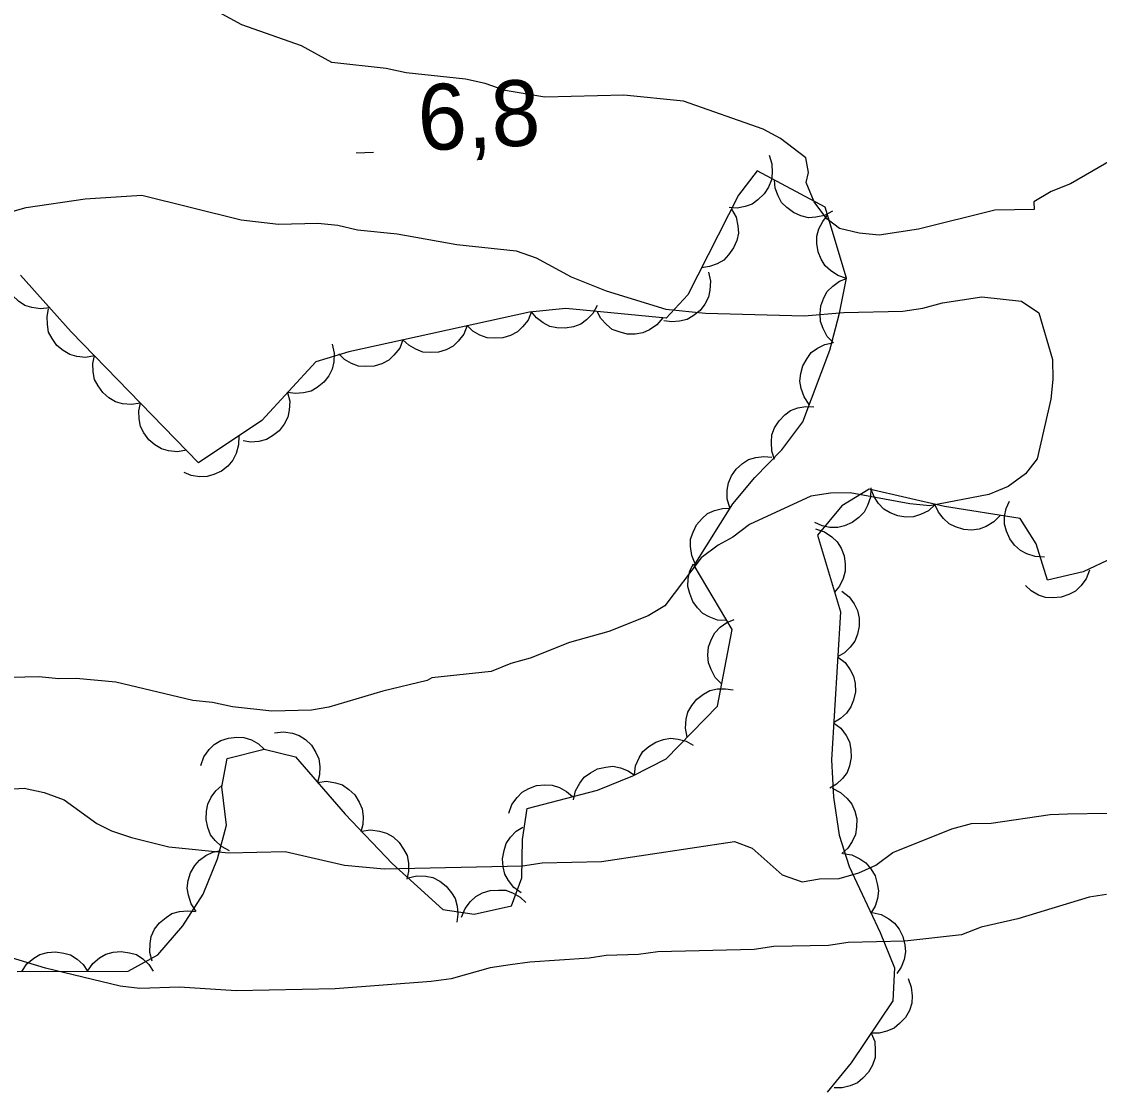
# Model space of a CAD drawing. Extents: x 336540 to 340074, y 5572036 to 5573747.
# Drawn here: x 337234.82 to 337283.95, y 5572869.46 to 5572918.23 of the extents above; entities that cross this region are included whole.
import ezdxf

# ---------------------------------------------------------------- set-up
doc = ezdxf.new("R2010")
doc.units = 0
for name, color, linetype in [('Niveau 2', 7, 'Continuous'), ('Niveau 3', 7, 'Continuous'), ('Niveau 44', 7, 'Continuous')]:
    doc.layers.add(name, color=color, linetype=linetype)

msp = doc.modelspace()

# ---------------------------------------------------------------- linework, layer by layer
at = {"layer": 'Niveau 2'}
for points in [[(337284.86, 5572912.13), (337282.63, 5572910.84), (337281.74, 5572910.48), (337280.96, 5572910.01), (337280.97, 5572909.67), (337279.17, 5572909.63), (337275.7, 5572908.76), (337273.9, 5572908.5), (337273, 5572908.59), (337272.09, 5572908.79), (337271.52, 5572909.23), (337270.94, 5572910.01), (337270.58, 5572910.9), (337270.68, 5572911.35), (337270.56, 5572912.02), (337269.41, 5572912.9), (337268.61, 5572913.33), (337264.98, 5572914.6), (337262.27, 5572914.88), (337258.67, 5572914.79), (337256.86, 5572915.09), (337255.95, 5572915.41), (337255.05, 5572915.61), (337252.34, 5572915.89), (337251.43, 5572916.09), (337248.95, 5572916.37), (337247.58, 5572917.13), (337244.85, 5572918.08), (337243.26, 5572918.95)], [(337234.12, 5572909.5), (337235.02, 5572909.75), (337237.71, 5572910.15), (337240.3, 5572910.32), (337244.83, 5572909.19), (337246.52, 5572909), (337248.32, 5572909.04), (337249.23, 5572908.95), (337250.13, 5572908.74), (337251.94, 5572908.56), (337254.65, 5572908.06), (337257.36, 5572907.78), (337258.27, 5572907.46), (337259.87, 5572906.6), (337261.46, 5572905.96), (337264.18, 5572905.12), (337265.99, 5572904.94), (337270.49, 5572904.81), (337272.29, 5572904.97), (337274.99, 5572905.03), (337275.89, 5572905.16), (337276.79, 5572905.41), (337278.58, 5572905.68), (337280.39, 5572905.49), (337281.19, 5572904.95), (337281.8, 5572902.82), (337281.82, 5572901.92), (337281.73, 5572901.02), (337281.11, 5572898.3)], [(337281.11, 5572898.3), (337280.57, 5572897.61), (337279.79, 5572897.03), (337278.9, 5572896.67), (337276.21, 5572896.16), (337275.3, 5572896.25), (337272.59, 5572896.75), (337271.69, 5572896.73), (337270.79, 5572896.6), (337268, 5572895.3), (337267.23, 5572894.72), (337266.56, 5572894.36), (337265.79, 5572893.78), (337264.14, 5572891.6), (337263.37, 5572891.14), (337261.58, 5572890.42), (337259.79, 5572889.93), (337258, 5572889.21), (337257.11, 5572888.97), (337256.22, 5572888.61), (337253.52, 5572888.32), (337253.3, 5572888.2), (337251.28, 5572887.71), (337248.82, 5572886.98), (337248.03, 5572886.84), (337246.23, 5572886.8), (337244.43, 5572886.99), (337243.52, 5572887.19), (337242.62, 5572887.28), (337239.11, 5572888.11), (337237.3, 5572888.29), (337236.51, 5572888.27), (337235.61, 5572888.36), (337233.02, 5572888.3)], [(337232.24, 5572883.11), (337234.94, 5572883.28), (337235.84, 5572883.08), (337236.75, 5572882.76), (337238.24, 5572881.67), (337238.92, 5572881.34), (337239.83, 5572881.03), (337241.53, 5572880.61), (337244.24, 5572880.34), (337246.83, 5572880.4), (337249.54, 5572879.78), (337251.35, 5572879.6), (337257.65, 5572879.74), (337258.55, 5572879.88), (337261.25, 5572879.94), (337267.31, 5572880.86), (337268.11, 5572880.55), (337269.49, 5572879.34), (337270.4, 5572879.02), (337271.18, 5572879.15), (337272.08, 5572879.17), (337272.98, 5572879.42), (337273.76, 5572879.77), (337274.53, 5572880.35), (337277.21, 5572881.43), (337278.11, 5572881.67), (337279.01, 5572881.69), (337281.7, 5572882.09), (337282.49, 5572882.11), (337284.29, 5572882.15)], [(337284.26, 5572878.44), (337283.48, 5572878.31), (337280.23, 5572877.33), (337278.55, 5572876.95), (337277.66, 5572876.6), (337275.08, 5572876.31), (337272.49, 5572876.25), (337271.59, 5572876.12), (337269.11, 5572876.06), (337268.21, 5572875.93), (337263.82, 5572875.83), (337262.93, 5572875.7), (337261.46, 5572875.66), (337260.68, 5572875.53), (337257.98, 5572875.36)], [(337257.98, 5572875.36), (337257.08, 5572875.23), (337256.18, 5572875.09), (337254.39, 5572874.6), (337253.49, 5572874.47), (337249.11, 5572874.14), (337244.6, 5572874.04), (337242.01, 5572874.21), (337240.21, 5572874.16), (337239.31, 5572874.26), (337235.91, 5572875.08), (337234.21, 5572875.6)]]:
    msp.add_lwpolyline(points, dxfattribs=at)
at = {"layer": 'Niveau 3'}
msp.add_line((337250.06, 5572912.24), (337250.86, 5572912.28), dxfattribs=at)
at = {"layer": 'Niveau 44'}
for points in [[(337268.89, 5572912.14), (337269.02, 5572911.74), (337269.03, 5572911.33), (337269, 5572911.01), (337268.86, 5572910.68), (337268.67, 5572910.37), (337268.38, 5572910.11), (337268.12, 5572909.91), (337267.79, 5572909.8), (337267.43, 5572909.73), (337267.07, 5572909.75)], [(337234.61, 5572874.93), (337239.67, 5572874.95), (337241.02, 5572875.69), (337242.17, 5572877.01), (337243.09, 5572878.45), (337243.74, 5572880.07), (337244.16, 5572881.6), (337243.95, 5572883.34), (337244.18, 5572884.63), (337245.87, 5572885.07), (337247.3, 5572884.71), (337249.57, 5572882.1), (337251.7, 5572879.85), (337254.01, 5572877.76), (337255.44, 5572877.54), (337257.14, 5572877.92), (337257.61, 5572879.19), (337257.65, 5572880.95), (337257.86, 5572882.36), (337261.06, 5572883.19), (337262.68, 5572883.85), (337264.19, 5572884.62), (337266.53, 5572887.02), (337267.2, 5572890.52), (337265.48, 5572893.44), (337267.24, 5572896.24), (337268.24, 5572897.45), (337269.47, 5572898.7), (337270.42, 5572899.99), (337271.65, 5572903.25), (337272.1, 5572904.94), (337272.42, 5572906.53), (337271.44, 5572909.77), (337268.34, 5572911.42), (337267.5, 5572910.32), (337265.18, 5572905.78), (337264.2, 5572904.71), (337259.63, 5572905.15), (337257.96, 5572904.99), (337249.73, 5572903.18), (337248.23, 5572902.72), (337245.76, 5572900.04), (337242.88, 5572898.12), (337237.08, 5572904.08), (337234.77, 5572906.67)], [(337271.78, 5572909.59), (337271.42, 5572909.39), (337271.02, 5572909.31), (337270.69, 5572909.29), (337270.34, 5572909.37), (337270, 5572909.52), (337269.7, 5572909.75), (337269.46, 5572909.98), (337269.3, 5572910.29), (337269.17, 5572910.64), (337269.14, 5572911)], [(337267.18, 5572909.68), (337267.38, 5572909.32), (337267.46, 5572908.92), (337267.49, 5572908.59), (337267.41, 5572908.25), (337267.27, 5572907.91), (337267.04, 5572907.6), (337266.82, 5572907.36), (337266.52, 5572907.18), (337266.17, 5572907.06), (337265.81, 5572907.01)], [(337272.42, 5572906.52), (337272.02, 5572906.65), (337271.69, 5572906.88), (337271.44, 5572907.1), (337271.26, 5572907.4), (337271.12, 5572907.74), (337271.07, 5572908.12), (337271.06, 5572908.45), (337271.16, 5572908.78), (337271.33, 5572909.12), (337271.55, 5572909.4)], [(337236.1, 5572905.18), (337235.68, 5572905.13), (337235.28, 5572905.19), (337234.97, 5572905.29), (337234.67, 5572905.48), (337234.4, 5572905.74), (337234.2, 5572906.06), (337234.06, 5572906.35), (337234, 5572906.7), (337234.01, 5572907.07), (337234.1, 5572907.42)], [(337266.12, 5572906.8), (337266.21, 5572906.39), (337266.19, 5572905.99), (337266.12, 5572905.66), (337265.96, 5572905.35), (337265.74, 5572905.06), (337265.43, 5572904.82), (337265.16, 5572904.65), (337264.81, 5572904.57), (337264.45, 5572904.54), (337264.09, 5572904.59)], [(337271.83, 5572903.58), (337271.53, 5572903.88), (337271.35, 5572904.24), (337271.23, 5572904.55), (337271.21, 5572904.9), (337271.25, 5572905.27), (337271.39, 5572905.63), (337271.54, 5572905.92), (337271.79, 5572906.17), (337272.09, 5572906.39), (337272.42, 5572906.52)], [(337238.14, 5572902.99), (337237.73, 5572902.92), (337237.33, 5572902.96), (337237.01, 5572903.05), (337236.71, 5572903.23), (337236.43, 5572903.47), (337236.21, 5572903.78), (337236.05, 5572904.07), (337235.99, 5572904.42), (337235.98, 5572904.79), (337236.05, 5572905.14)], [(337258.06, 5572905.01), (337257.91, 5572904.62), (337257.65, 5572904.31), (337257.42, 5572904.08), (337257.1, 5572903.92), (337256.75, 5572903.81), (337256.37, 5572903.79), (337256.04, 5572903.81), (337255.71, 5572903.93), (337255.39, 5572904.12), (337255.13, 5572904.37)], [(337261.05, 5572905.29), (337260.85, 5572904.92), (337260.56, 5572904.63), (337260.3, 5572904.44), (337259.97, 5572904.31), (337259.6, 5572904.25), (337259.22, 5572904.27), (337258.9, 5572904.33), (337258.59, 5572904.5), (337258.29, 5572904.72), (337258.06, 5572905)], [(337264.04, 5572904.73), (337263.77, 5572904.4), (337263.43, 5572904.18), (337263.13, 5572904.04), (337262.79, 5572903.98), (337262.42, 5572903.98), (337262.05, 5572904.08), (337261.74, 5572904.2), (337261.47, 5572904.42), (337261.22, 5572904.7), (337261.05, 5572905.01)], [(337255.13, 5572904.37), (337254.98, 5572903.98), (337254.72, 5572903.66), (337254.49, 5572903.43), (337254.17, 5572903.27), (337253.82, 5572903.16), (337253.44, 5572903.14), (337253.11, 5572903.16), (337252.78, 5572903.29), (337252.46, 5572903.48), (337252.2, 5572903.72)], [(337248.98, 5572903.53), (337249.07, 5572903.12), (337249.05, 5572902.72), (337248.98, 5572902.39), (337248.82, 5572902.08), (337248.59, 5572901.79), (337248.29, 5572901.55), (337248.01, 5572901.38), (337247.67, 5572901.3), (337247.3, 5572901.27), (337246.94, 5572901.32)], [(337252.2, 5572903.72), (337252.05, 5572903.34), (337251.79, 5572903.02), (337251.56, 5572902.79), (337251.24, 5572902.63), (337250.89, 5572902.52), (337250.51, 5572902.5), (337250.18, 5572902.52), (337249.85, 5572902.64), (337249.53, 5572902.83), (337249.27, 5572903.08)], [(337270.72, 5572900.78), (337270.48, 5572901.13), (337270.35, 5572901.51), (337270.29, 5572901.84), (337270.33, 5572902.19), (337270.43, 5572902.54), (337270.62, 5572902.87), (337270.81, 5572903.14), (337271.1, 5572903.34), (337271.43, 5572903.51), (337271.78, 5572903.59)], [(337240.23, 5572900.84), (337239.82, 5572900.77), (337239.42, 5572900.81), (337239.1, 5572900.9), (337238.8, 5572901.08), (337238.52, 5572901.32), (337238.3, 5572901.63), (337238.14, 5572901.92), (337238.08, 5572902.27), (337238.07, 5572902.64), (337238.14, 5572902.99)], [(337246.94, 5572901.32), (337247.04, 5572900.92), (337247.01, 5572900.51), (337246.95, 5572900.19), (337246.78, 5572899.88), (337246.56, 5572899.58), (337246.25, 5572899.35), (337245.98, 5572899.18), (337245.63, 5572899.09), (337245.27, 5572899.06), (337244.91, 5572899.12)], [(337242.33, 5572898.69), (337241.92, 5572898.62), (337241.51, 5572898.66), (337241.19, 5572898.75), (337240.89, 5572898.93), (337240.61, 5572899.17), (337240.39, 5572899.48), (337240.24, 5572899.77), (337240.17, 5572900.12), (337240.16, 5572900.49), (337240.23, 5572900.84)], [(337269.14, 5572898.26), (337269.01, 5572898.65), (337268.99, 5572899.06), (337269.02, 5572899.39), (337269.14, 5572899.71), (337269.34, 5572900.03), (337269.61, 5572900.3), (337269.87, 5572900.5), (337270.2, 5572900.62), (337270.56, 5572900.69), (337270.92, 5572900.67)], [(337244.72, 5572899.34), (337244.71, 5572898.93), (337244.59, 5572898.54), (337244.45, 5572898.24), (337244.22, 5572897.97), (337243.93, 5572897.74), (337243.58, 5572897.59), (337243.27, 5572897.49), (337242.92, 5572897.48), (337242.55, 5572897.54), (337242.22, 5572897.68)], [(337267.1, 5572896.07), (337266.98, 5572896.47), (337266.98, 5572896.87), (337267.03, 5572897.2), (337267.18, 5572897.52), (337267.39, 5572897.82), (337267.68, 5572898.08), (337267.95, 5572898.26), (337268.28, 5572898.36), (337268.65, 5572898.41), (337269.01, 5572898.38)], [(337273.53, 5572896.97), (337273.51, 5572896.55), (337273.37, 5572896.17), (337273.22, 5572895.87), (337272.98, 5572895.62), (337272.68, 5572895.4), (337272.33, 5572895.25), (337272.02, 5572895.16), (337271.66, 5572895.17), (337271.3, 5572895.25), (337270.97, 5572895.39)], [(337284.55, 5572893.79), (337283.2, 5572893.15), (337281.58, 5572892.76), (337281.06, 5572894.42), (337280.33, 5572895.58), (337276.88, 5572896.12), (337273.45, 5572896.92), (337272.2, 5572896.15), (337271.09, 5572894.82), (337272.14, 5572891.33), (337271.73, 5572884.57), (337271.83, 5572882.87), (337272.08, 5572881.14), (337272.53, 5572879.71), (337273.95, 5572876.71), (337274.61, 5572875.09), (337274.53, 5572873.59), (337272.63, 5572870.77), (337271.53, 5572869.42)], [(337276.46, 5572896.22), (337276.15, 5572895.93), (337275.79, 5572895.76), (337275.47, 5572895.65), (337275.12, 5572895.64), (337274.75, 5572895.7), (337274.4, 5572895.84), (337274.12, 5572896), (337273.87, 5572896.26), (337273.67, 5572896.56), (337273.54, 5572896.9)], [(337265.52, 5572893.51), (337265.36, 5572893.89), (337265.31, 5572894.3), (337265.31, 5572894.63), (337265.42, 5572894.96), (337265.58, 5572895.29), (337265.84, 5572895.58), (337266.08, 5572895.8), (337266.4, 5572895.94), (337266.76, 5572896.04), (337267.12, 5572896.05)], [(337279.42, 5572895.72), (337279.13, 5572895.42), (337278.78, 5572895.21), (337278.47, 5572895.09), (337278.12, 5572895.05), (337277.76, 5572895.08), (337277.39, 5572895.2), (337277.1, 5572895.33), (337276.84, 5572895.57), (337276.61, 5572895.86), (337276.45, 5572896.19)], [(337281.44, 5572893.82), (337281.02, 5572893.84), (337280.63, 5572893.97), (337280.34, 5572894.12), (337280.08, 5572894.36), (337279.86, 5572894.65), (337279.71, 5572895), (337279.62, 5572895.32), (337279.62, 5572895.67), (337279.69, 5572896.03), (337279.84, 5572896.36)], [(337271.01, 5572895.1), (337271.41, 5572894.97), (337271.74, 5572894.74), (337271.99, 5572894.52), (337272.17, 5572894.22), (337272.31, 5572893.88), (337272.36, 5572893.5), (337272.36, 5572893.17), (337272.26, 5572892.84), (337272.1, 5572892.5), (337271.87, 5572892.22)], [(337266.96, 5572890.93), (337266.54, 5572890.95), (337266.16, 5572891.09), (337265.87, 5572891.25), (337265.62, 5572891.5), (337265.41, 5572891.8), (337265.27, 5572892.16), (337265.19, 5572892.47), (337265.2, 5572892.82), (337265.28, 5572893.19), (337265.44, 5572893.51)], [(337283.49, 5572893.22), (337283.34, 5572892.83), (337283.1, 5572892.51), (337282.86, 5572892.27), (337282.55, 5572892.11), (337282.2, 5572891.99), (337281.82, 5572891.96), (337281.49, 5572891.97), (337281.16, 5572892.09), (337280.84, 5572892.28), (337280.57, 5572892.52)], [(337272.2, 5572892.26), (337272.53, 5572892.01), (337272.76, 5572891.68), (337272.92, 5572891.38), (337272.99, 5572891.04), (337273, 5572890.67), (337272.91, 5572890.3), (337272.8, 5572889.99), (337272.59, 5572889.71), (337272.32, 5572889.45), (337272.01, 5572889.27)], [(337266.72, 5572888.04), (337266.43, 5572888.33), (337266.24, 5572888.69), (337266.12, 5572889), (337266.1, 5572889.35), (337266.13, 5572889.72), (337266.27, 5572890.08), (337266.41, 5572890.37), (337266.66, 5572890.62), (337266.96, 5572890.84), (337267.29, 5572890.98)], [(337272.01, 5572889.27), (337272.35, 5572889.01), (337272.58, 5572888.68), (337272.74, 5572888.39), (337272.81, 5572888.05), (337272.82, 5572887.68), (337272.73, 5572887.3), (337272.62, 5572886.99), (337272.41, 5572886.71), (337272.14, 5572886.46), (337271.83, 5572886.27)], [(337265.16, 5572885.61), (337265.07, 5572886.02), (337265.11, 5572886.43), (337265.18, 5572886.75), (337265.36, 5572887.06), (337265.59, 5572887.34), (337265.9, 5572887.57), (337266.18, 5572887.73), (337266.53, 5572887.81), (337266.9, 5572887.82), (337267.25, 5572887.76)], [(337271.83, 5572886.27), (337272.16, 5572886.02), (337272.4, 5572885.69), (337272.56, 5572885.4), (337272.62, 5572885.05), (337272.63, 5572884.68), (337272.55, 5572884.31), (337272.44, 5572884), (337272.23, 5572883.72), (337271.96, 5572883.46), (337271.65, 5572883.28)], [(337246.34, 5572885.81), (337246.76, 5572885.86), (337247.16, 5572885.79), (337247.47, 5572885.69), (337247.76, 5572885.5), (337248.03, 5572885.24), (337248.23, 5572884.91), (337248.37, 5572884.62), (337248.41, 5572884.27), (337248.4, 5572883.9), (337248.31, 5572883.55)], [(337242.98, 5572884.32), (337243.12, 5572884.71), (337243.36, 5572885.04), (337243.59, 5572885.28), (337243.9, 5572885.45), (337244.24, 5572885.57), (337244.63, 5572885.61), (337244.95, 5572885.6), (337245.29, 5572885.49), (337245.61, 5572885.31), (337245.88, 5572885.07)], [(337262.75, 5572883.89), (337262.8, 5572884.3), (337262.97, 5572884.67), (337263.14, 5572884.95), (337263.4, 5572885.19), (337263.72, 5572885.38), (337264.08, 5572885.5), (337264.4, 5572885.56), (337264.75, 5572885.52), (337265.11, 5572885.42), (337265.43, 5572885.25)], [(337259.98, 5572882.75), (337260.06, 5572883.16), (337260.26, 5572883.51), (337260.46, 5572883.78), (337260.74, 5572883.99), (337261.07, 5572884.16), (337261.44, 5572884.24), (337261.76, 5572884.28), (337262.11, 5572884.21), (337262.46, 5572884.08), (337262.76, 5572883.88)], [(337244.3, 5572880.43), (337243.93, 5572880.62), (337243.64, 5572880.9), (337243.43, 5572881.16), (337243.3, 5572881.49), (337243.23, 5572881.85), (337243.25, 5572882.24), (337243.3, 5572882.56), (337243.45, 5572882.87), (337243.67, 5572883.17), (337243.94, 5572883.41)], [(337248.31, 5572883.55), (337248.72, 5572883.6), (337249.12, 5572883.53), (337249.44, 5572883.43), (337249.73, 5572883.23), (337250, 5572882.98), (337250.2, 5572882.65), (337250.34, 5572882.35), (337250.38, 5572882), (337250.37, 5572881.63), (337250.28, 5572881.29)], [(337257.02, 5572882.14), (337257.16, 5572882.54), (337257.41, 5572882.86), (337257.64, 5572883.1), (337257.94, 5572883.27), (337258.29, 5572883.4), (337258.67, 5572883.43), (337259, 5572883.42), (337259.33, 5572883.31), (337259.66, 5572883.13), (337259.93, 5572882.9)], [(337271.77, 5572883.28), (337272.15, 5572883.09), (337272.45, 5572882.82), (337272.66, 5572882.56), (337272.79, 5572882.24), (337272.88, 5572881.88), (337272.87, 5572881.5), (337272.83, 5572881.17), (337272.68, 5572880.85), (337272.47, 5572880.55), (337272.2, 5572880.31)], [(337250.31, 5572881.32), (337250.72, 5572881.38), (337251.13, 5572881.33), (337251.45, 5572881.24), (337251.75, 5572881.06), (337252.02, 5572880.81), (337252.23, 5572880.5), (337252.39, 5572880.21), (337252.45, 5572879.86), (337252.45, 5572879.49), (337252.37, 5572879.14)], [(337257.59, 5572878.51), (337257.25, 5572878.75), (337257.01, 5572879.08), (337256.84, 5572879.36), (337256.76, 5572879.7), (337256.73, 5572880.07), (337256.81, 5572880.45), (337256.9, 5572880.76), (337257.1, 5572881.05), (337257.36, 5572881.32), (337257.66, 5572881.51)], [(337242.78, 5572877.67), (337242.54, 5572878.01), (337242.42, 5572878.4), (337242.37, 5572878.73), (337242.41, 5572879.07), (337242.52, 5572879.43), (337242.72, 5572879.76), (337242.92, 5572880.01), (337243.21, 5572880.21), (337243.54, 5572880.37), (337243.89, 5572880.45)], [(337272.25, 5572880.3), (337272.66, 5572880.24), (337273.03, 5572880.06), (337273.3, 5572879.88), (337273.53, 5572879.61), (337273.72, 5572879.29), (337273.82, 5572878.93), (337273.88, 5572878.6), (337273.83, 5572878.26), (337273.72, 5572877.9), (337273.53, 5572877.59)], [(337252.43, 5572879.19), (337252.83, 5572879.29), (337253.24, 5572879.27), (337253.56, 5572879.21), (337253.88, 5572879.05), (337254.17, 5572878.82), (337254.41, 5572878.52), (337254.58, 5572878.25), (337254.67, 5572877.9), (337254.7, 5572877.54), (337254.65, 5572877.18)], [(337254.87, 5572877.41), (337255.03, 5572877.8), (337255.28, 5572878.12), (337255.52, 5572878.35), (337255.83, 5572878.51), (337256.18, 5572878.62), (337256.56, 5572878.64), (337256.89, 5572878.63), (337257.22, 5572878.5), (337257.54, 5572878.31), (337257.8, 5572878.07)], [(337240.77, 5572875.4), (337240.66, 5572875.8), (337240.67, 5572876.21), (337240.73, 5572876.53), (337240.88, 5572876.85), (337241.1, 5572877.15), (337241.4, 5572877.39), (337241.67, 5572877.57), (337242.01, 5572877.66), (337242.38, 5572877.7), (337242.74, 5572877.66)], [(337273.58, 5572877.61), (337273.99, 5572877.53), (337274.35, 5572877.33), (337274.61, 5572877.13), (337274.82, 5572876.85), (337274.99, 5572876.53), (337275.08, 5572876.15), (337275.11, 5572875.83), (337275.04, 5572875.48), (337274.91, 5572875.13), (337274.71, 5572874.84)], [(337237.82, 5572874.94), (337238.06, 5572875.29), (337238.37, 5572875.55), (337238.65, 5572875.72), (337238.99, 5572875.81), (337239.36, 5572875.84), (337239.74, 5572875.78), (337240.05, 5572875.7), (337240.35, 5572875.5), (337240.62, 5572875.25), (337240.82, 5572874.95)], [(337234.82, 5572874.93), (337235.06, 5572875.28), (337235.37, 5572875.54), (337235.65, 5572875.71), (337235.99, 5572875.8), (337236.36, 5572875.83), (337236.74, 5572875.77), (337237.05, 5572875.68), (337237.35, 5572875.49), (337237.62, 5572875.24), (337237.82, 5572874.94)], [(337275.22, 5572874.61), (337275.37, 5572874.22), (337275.41, 5572873.82), (337275.39, 5572873.49), (337275.28, 5572873.15), (337275.1, 5572872.83), (337274.83, 5572872.55), (337274.59, 5572872.34), (337274.26, 5572872.21), (337273.9, 5572872.12), (337273.54, 5572872.12)], [(337273.54, 5572872.12), (337273.7, 5572871.73), (337273.73, 5572871.33), (337273.72, 5572871), (337273.6, 5572870.66), (337273.42, 5572870.34), (337273.16, 5572870.06), (337272.91, 5572869.85), (337272.58, 5572869.72), (337272.22, 5572869.63), (337271.86, 5572869.63)]]:
    msp.add_lwpolyline(points, dxfattribs=at)

# ---------------------------------------------------------------- texts
at = {"layer": 'Niveau 3'}
msp.add_text('6,8    ', height=3, rotation=2.7712, dxfattribs=at).set_placement((337252.94, 5572912.34))

doc.saveas('drawing.dxf')
